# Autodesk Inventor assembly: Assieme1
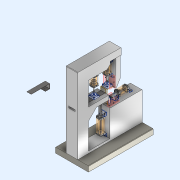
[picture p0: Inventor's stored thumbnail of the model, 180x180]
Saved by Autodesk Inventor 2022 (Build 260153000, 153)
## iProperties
Created: 2022-01
Part Number: Assieme1
Document SubType Name: Assembly
Designer: admin
Author: admin
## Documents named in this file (16)
- C:\Users\admin\Desktop\inventor\sistema_piegatura2\Assieme_piegatura.iam
- C:\Users\admin\Desktop\inventor\sistema_piegatura2\telaio.ipt
- C:\Users\admin\Desktop\inventor\sistema_piegatura2\2500320050CP_0-0-0-A--2.iam
- C:\Users\admin\Desktop\inventor\sistema_piegatura2\2500320050CP_0-0-0-A--C.iam
- C:\Users\admin\Desktop\inventor\sistema_piegatura2\2300320100FP_0-GA-M-0-A-0-0_B.iam
- C:\Users\admin\Desktop\inventor\sistema_piegatura2\punta_fustella.ipt
- C:\Users\admin\Desktop\inventor\sistema_piegatura2\lamiera.ipt
- C:\Users\admin\Desktop\inventor\sistema_piegatura2\guida_1.ipt
- C:\Users\admin\Desktop\inventor\sistema_piegatura2\punzone1.ipt
- C:\Users\admin\Desktop\inventor\sistema_piegatura2\punzone2.ipt
- C:\Users\admin\Desktop\inventor\sistema_piegatura2\gomma_blocco.ipt
- C:\Users\admin\Documents\Inventor\Content Center Files\R2022\it-IT\AS 1420\AS 1420 - 1973 - M4 x 20.ipt
- C:\Users\admin\Documents\Inventor\Content Center Files\R2022\it-IT\AS 1420\AS 1420 - 1973 - M6 x 14.ipt
- C:\Users\admin\Documents\Inventor\Content Center Files\R2022\it-IT\AS 1420\AS 1420 - 1973 - M5 x 10.ipt
- C:\Users\admin\Documents\Inventor\Content Center Files\R2022\it-IT\AS 1420\AS 1420 - 1973 - M6 x 16.ipt
- C:\Users\admin\Documents\Inventor\Content Center Files\R2022\it-IT\AS 1420\AS 1420 - 1973 - M4 x 8.ipt
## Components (41 placed, 15 different names)
1. telaio:1 — Allineato:5, Coincidente:5, Allineato:6, Coincidente:6, Coincidente:7, Coincidente:9, Allineato:11, Allineato:12, Coincidente:10, Coincidente:11, Coincidente:12, Allineato:14, Coincidente:13, Allineato:16, Coincidente:14, Allineato:17, Coincidente:16, Allineato:18
2. 2500320050CP_0-0-0-A--2:2 [sub-assembly] — Coincidente:5, Allineato:6, Coincidente:6, Allineato:7, Coincidente:22, Allineato:20, Allineato:21
3. 2500320050CP_0-0-0-A--C:1 [sub-assembly] — Coincidente:7, Allineato:7, Coincidente:10, Allineato:15, Coincidente:18, Allineato:19
4. 2300320100FP_0-GA-M-0-A-0-0_B:1 [sub-assembly] — Coincidente:9, Allineato:11, Allineato:12, Rotazionale:1
5. punta_fustella:1 — Rotazionale:1
6. lamiera:1 — Coincidente:11, Coincidente:12, Allineato:14
7. 2500320050CP_0-0-0-A--C:2 [sub-assembly] — Coincidente:13, Allineato:15, Allineato:16, Coincidente:15, Coincidente:19, Coincidente:20, Coincidente:21
8. guida_1:1 — Coincidente:14, Allineato:17, Coincidente:15
9. guida_1:2 — Coincidente:16, Coincidente:18, Allineato:18
10. punzone1:1 — Allineato:19
11. punzone2:1 — Coincidente:19, Coincidente:20, Coincidente:21
12. gomma_blocco:1 — Coincidente:22, Allineato:20, Allineato:21
13. lamiera:2
14. AS 1420 - Metrico M4 x 20:1
15. AS 1420 - Metrico M4 x 20:2
16. AS 1420 - Metrico M4 x 20:3
17. AS 1420 - Metrico M4 x 20:4
18. AS 1420 - Metrico M4 x 20:5
19. AS 1420 - Metrico M4 x 20:6
20. AS 1420 - Metrico M4 x 20:7
21. AS 1420 - Metrico M6 x 14:1
22. AS 1420 - Metrico M6 x 14:2
23. AS 1420 - Metrico M6 x 14:3
24. AS 1420 - Metrico M6 x 14:4
25. AS 1420 - Metrico M6 x 14:5
26. AS 1420 - Metrico M6 x 14:6
27. AS 1420 - Metrico M6 x 14:7
28. AS 1420 - Metrico M6 x 14:8
29. AS 1420 - Metrico M5 x 10:1
30. AS 1420 - Metrico M5 x 10:2
31. AS 1420 - Metrico M5 x 10:3
32. AS 1420 - Metrico M5 x 10:4
33. AS 1420 - Metrico M6 x 16:1
34. AS 1420 - Metrico M6 x 16:2
35. AS 1420 - Metrico M6 x 16:3
36. AS 1420 - Metrico M6 x 16:4
37. AS 1420 - Metrico M4 x 8:1
38. AS 1420 - Metrico M4 x 8:2
39. AS 1420 - Metrico M4 x 8:3
40. AS 1420 - Metrico M4 x 8:4
41. AS 1420 - Metrico M4 x 8:5
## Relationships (30: Mate 16, Flush 13, RevoluteJoint 1)
- Allineato:5 [Flush]: telaio:1
- Coincidente:5 [Mate]: telaio:1 ↔ 2500320050CP_0-0-0-A--2:2
- Allineato:6 [Flush]: telaio:1 ↔ 2500320050CP_0-0-0-A--2:2
- Coincidente:6 [Mate]: telaio:1 ↔ 2500320050CP_0-0-0-A--2:2
- Coincidente:7 [Mate]: telaio:1 ↔ 2500320050CP_0-0-0-A--C:1
- Allineato:7 [Flush]: 2500320050CP_0-0-0-A--2:2 ↔ 2500320050CP_0-0-0-A--C:1
- Coincidente:9 [Mate]: telaio:1 ↔ 2300320100FP_0-GA-M-0-A-0-0_B:1
- Allineato:11 [Flush]: telaio:1 ↔ 2300320100FP_0-GA-M-0-A-0-0_B:1
- Allineato:12 [Flush]: telaio:1 ↔ 2300320100FP_0-GA-M-0-A-0-0_B:1
- Coincidente:10 [Mate]: telaio:1 ↔ 2500320050CP_0-0-0-A--C:1
- Rotazionale:1 [RevoluteJoint]: 2300320100FP_0-GA-M-0-A-0-0_B:1 ↔ punta_fustella:1
- Coincidente:11 [Mate]: telaio:1 ↔ lamiera:1
- Coincidente:12 [Mate]: telaio:1 ↔ lamiera:1
- Allineato:14 [Flush]: telaio:1 ↔ lamiera:1
- Coincidente:13 [Mate]: telaio:1 ↔ 2500320050CP_0-0-0-A--C:2
- Allineato:15 [Flush]: 2500320050CP_0-0-0-A--C:1 ↔ 2500320050CP_0-0-0-A--C:2
- Allineato:16 [Flush]: telaio:1 ↔ 2500320050CP_0-0-0-A--C:2
- Coincidente:14 [Mate]: telaio:1 ↔ guida_1:1
- Allineato:17 [Flush]: telaio:1 ↔ guida_1:1
- Coincidente:15 [Mate]: 2500320050CP_0-0-0-A--C:2 ↔ guida_1:1
- Coincidente:16 [Mate]: telaio:1 ↔ guida_1:2
- Coincidente:18 [Mate]: 2500320050CP_0-0-0-A--C:1 ↔ guida_1:2
- Allineato:18 [Flush]: telaio:1 ↔ guida_1:2
- Allineato:19 [Flush]: 2500320050CP_0-0-0-A--C:1 ↔ punzone1:1
- Coincidente:19 [Mate]: 2500320050CP_0-0-0-A--C:2 ↔ punzone2:1
- Coincidente:20 [Mate]: 2500320050CP_0-0-0-A--C:2 ↔ punzone2:1
- Coincidente:21 [Mate]: 2500320050CP_0-0-0-A--C:2 ↔ punzone2:1
- Coincidente:22 [Mate]: 2500320050CP_0-0-0-A--2:2 ↔ gomma_blocco:1
- Allineato:20 [Flush]: 2500320050CP_0-0-0-A--2:2 ↔ gomma_blocco:1
- Allineato:21 [Flush]: 2500320050CP_0-0-0-A--2:2 ↔ gomma_blocco:1
